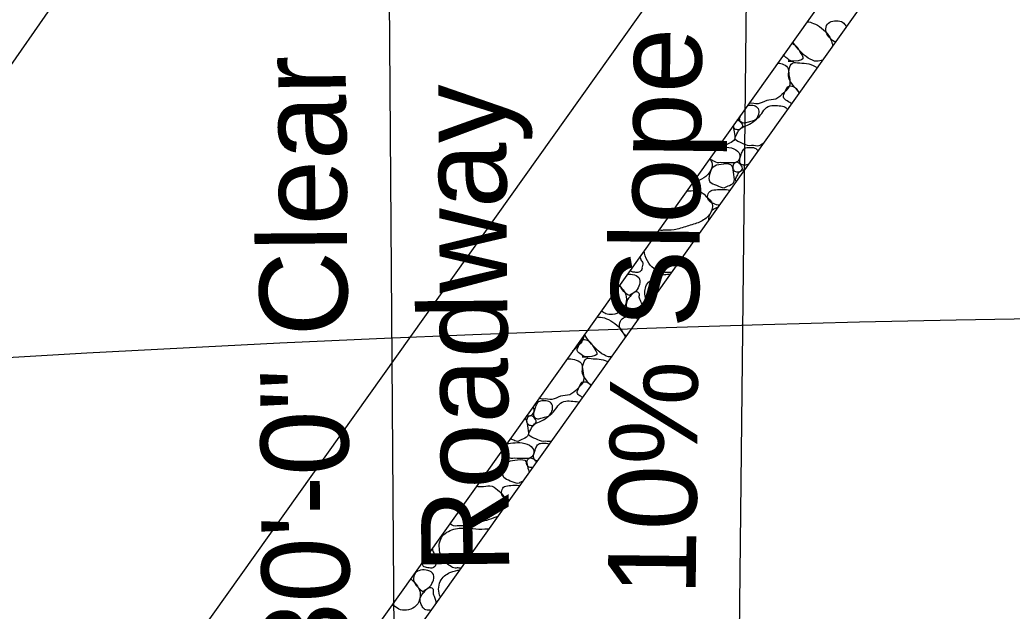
# Model space of a CAD drawing. Extents: x 1385284 to 1385995, y 1975154 to 1975620.
# Drawn here: x 1385473.66 to 1385501.91, y 1975481.13 to 1975497.97 of the extents above; entities that cross this region are included whole.
import ezdxf

# ---------------------------------------------------------------- set-up
doc = ezdxf.new("R2010")
doc.units = 0
for name, color, linetype in [('Default', 7, 'Continuous'), ('R_Horz Alg', 7, 'Continuous'), ('R_Proposed Const Limits', 7, 'Continuous'), ('R_Proposed Road', 7, 'Continuous')]:
    doc.layers.add(name, color=color, linetype=linetype)

msp = doc.modelspace()

# ---------------------------------------------------------------- linework, layer by layer
at = {"layer": 'Default'}
for p, q in [((1385485.913, 1975514.687), (1385460.044, 1975477.467)), ((1385494.416, 1975505.475), (1385494.049, 1975472.644)), ((1385500.579, 1975504.251), (1385472.911, 1975465.371)), ((1385484.136, 1975503.942), (1385484.353, 1975473.943)), ((1385473.726, 1975464.791), (1385501.394, 1975503.671))]:
    msp.add_line(p, q, dxfattribs=at)
for points in [[(1385496.074, 1975497.92), (1385496.093, 1975497.918), (1385496.205, 1975497.901), (1385496.416, 1975497.797), (1385496.673, 1975497.585), (1385496.774, 1975497.365), (1385496.804, 1975497.236), (1385496.806, 1975497.224)], [(1385496.89, 1975497.343), (1385496.839, 1975497.338), (1385496.678, 1975497.49), (1385496.584, 1975497.653), (1385496.634, 1975497.873), (1385496.798, 1975497.946), (1385497.026, 1975497.953), (1385497.155, 1975497.854), (1385497.189, 1975497.78), (1385497.192, 1975497.767)], [(1385495.635, 1975497.304), (1385495.645, 1975497.303), (1385495.706, 1975497.273), (1385495.813, 1975497.177), (1385495.88, 1975497.033), (1385496.067, 1975496.784), (1385495.318, 1975496.801), (1385495.704, 1975496.791), (1385495.695, 1975496.793)], [(1385496.344, 1975496.793), (1385496.273, 1975496.79), (1385496.09, 1975496.874), (1385495.893, 1975497.056), (1385495.749, 1975497.219), (1385495.673, 1975497.327), (1385495.663, 1975497.343)], [(1385495.662, 1975496.793), (1385495.614, 1975496.792), (1385495.518, 1975496.865), (1385495.421, 1975496.931), (1385495.405, 1975496.978), (1385495.405, 1975496.98)], [(1385495.235, 1975496.742), (1385495.269, 1975496.74), (1385495.352, 1975496.724), (1385495.551, 1975496.642), (1385495.543, 1975496.414), (1385495.629, 1975496.103), (1385495.415, 1975495.896), (1385495.193, 1975495.674), (1385494.917, 1975495.706), (1385494.68, 1975495.531), (1385494.514, 1975495.611), (1385494.435, 1975495.59)], [(1385495.861, 1975495.896), (1385495.802, 1975495.958), (1385495.672, 1975496.099), (1385495.525, 1975496.317), (1385495.557, 1975496.543), (1385495.628, 1975496.786), (1385495.857, 1975496.733), (1385496.121, 1975496.738), (1385496.291, 1975496.653), (1385496.367, 1975496.608)], [(1385496.524, 1975496.827), (1385496.464, 1975496.804), (1385496.404, 1975496.793), (1385496.344, 1975496.793)], [(1385495.644, 1975495.592), (1385495.602, 1975495.598), (1385495.512, 1975495.666), (1385495.355, 1975495.755), (1385495.465, 1975495.94), (1385495.512, 1975496.105), (1385495.693, 1975496.079), (1385495.793, 1975495.997), (1385495.832, 1975495.91), (1385495.846, 1975495.876)], [(1385494.435, 1975494.387), (1385494.364, 1975494.383), (1385494.228, 1975494.463), (1385493.969, 1975494.552), (1385494.083, 1975494.721), (1385494.162, 1975494.907), (1385494.386, 1975494.952), (1385494.587, 1975495.11), (1385494.766, 1975495.252), (1385494.861, 1975495.458), (1385495.072, 1975495.551), (1385495.288, 1975495.525), (1385495.468, 1975495.498), (1385495.507, 1975495.43), (1385495.516, 1975495.411)], [(1385494.378, 1975495.537), (1385494.384, 1975495.537), (1385494.462, 1975495.544), (1385494.603, 1975495.542), (1385494.716, 1975495.414), (1385494.692, 1975495.254), (1385494.631, 1975495.137), (1385494.578, 1975495.107)], [(1385494.435, 1975495.59), (1385494.429, 1975495.59), (1385494.422, 1975495.59), (1385494.416, 1975495.59)], [(1385494.168, 1975495.243), (1385494.168, 1975495.236), (1385494.16, 1975495.192), (1385494.128, 1975495.117), (1385494.078, 1975495.11), (1385494.073, 1975495.109)], [(1385494.078, 1975495.115), (1385494.112, 1975495.114), (1385494.186, 1975495.073), (1385494.272, 1975494.93), (1385494.184, 1975494.871), (1385494.15, 1975494.841)], [(1385494.578, 1975495.107), (1385494.531, 1975495.092), (1385494.435, 1975495.069), (1385494.3, 1975495.016), (1385494.173, 1975495.057), (1385494.145, 1975495.148), (1385494.158, 1975495.207), (1385494.167, 1975495.24)], [(1385493.964, 1975494.956), (1385493.98, 1975494.911), (1385493.993, 1975494.793), (1385494.047, 1975494.537), (1385493.863, 1975494.46), (1385493.76, 1975494.412), (1385493.712, 1975494.387)], [(1385494.15, 1975494.841), (1385494.113, 1975494.841), (1385494.028, 1975494.839), (1385493.977, 1975494.902), (1385493.96, 1975494.94), (1385493.958, 1975494.947)], [(1385493.712, 1975494.387), (1385493.669, 1975494.393), (1385493.627, 1975494.406), (1385493.584, 1975494.422)], [(1385494.828, 1975494.445), (1385494.781, 1975494.426), (1385494.665, 1975494.335), (1385494.514, 1975494.408), (1385494.435, 1975494.387)], [(1385493.524, 1975494.337), (1385493.634, 1975494.345), (1385493.857, 1975494.358), (1385494.129, 1975494.248), (1385494.188, 1975494.062), (1385494.092, 1975493.896), (1385493.887, 1975493.904), (1385493.727, 1975493.898), (1385493.607, 1975493.904)], [(1385494.413, 1975493.861), (1385494.372, 1975493.851), (1385494.292, 1975493.815), (1385494.173, 1975493.854), (1385494.146, 1975493.961), (1385494.177, 1975494.075), (1385494.22, 1975494.202), (1385494.281, 1975494.326), (1385494.431, 1975494.342), (1385494.596, 1975494.339), (1385494.665, 1975494.265), (1385494.681, 1975494.238)], [(1385493.299, 1975494.021), (1385493.319, 1975493.995), (1385493.417, 1975493.875), (1385493.313, 1975493.59), (1385493.071, 1975493.42), (1385492.906, 1975493.361), (1385492.808, 1975493.331)], [(1385493.712, 1975493.184), (1385493.64, 1975493.195), (1385493.495, 1975493.264), (1385493.272, 1975493.334), (1385493.275, 1975493.563), (1385493.385, 1975493.808), (1385493.601, 1975493.857), (1385493.962, 1975493.887), (1385493.965, 1975493.646), (1385494.047, 1975493.334), (1385493.863, 1975493.257), (1385493.76, 1975493.209), (1385493.712, 1975493.184)], [(1385493.607, 1975493.904), (1385493.551, 1975493.88), (1385493.425, 1975493.931), (1385493.335, 1975493.986), (1385493.3, 1975494.022)], [(1385494.15, 1975493.638), (1385494.113, 1975493.638), (1385494.028, 1975493.636), (1385493.949, 1975493.718), (1385493.957, 1975493.836), (1385494.041, 1975493.938), (1385494.168, 1975493.888), (1385494.272, 1975493.727), (1385494.184, 1975493.668), (1385494.15, 1975493.638)], [(1385494.058, 1975493.363), (1385494.049, 1975493.374), (1385494.015, 1975493.415), (1385494.083, 1975493.518), (1385494.143, 1975493.666), (1385494.253, 1975493.695), (1385494.308, 1975493.714)], [(1385492.645, 1975493.102), (1385492.664, 1975493.101), (1385492.767, 1975493.091), (1385492.983, 1975493.157), (1385493.187, 1975492.951), (1385493.439, 1975492.747), (1385493.313, 1975492.387), (1385493.025, 1975492.197), (1385492.656, 1975492.096), (1385492.285, 1975491.968), (1385492.052, 1975491.982), (1385491.979, 1975491.985)], [(1385493.582, 1975492.694), (1385493.532, 1975492.686), (1385493.4, 1975492.74), (1385493.245, 1975492.822), (1385493.234, 1975492.988), (1385493.311, 1975493.12), (1385493.531, 1975493.138), (1385493.725, 1975493.149), (1385493.875, 1975493.122), (1385493.885, 1975493.119)], [(1385493.275, 1975492.263), (1385493.273, 1975492.29), (1385493.287, 1975492.392), (1385493.368, 1975492.573), (1385493.492, 1975492.626), (1385493.547, 1975492.644)], [(1385491.756, 1975491.853), (1385491.794, 1975491.871), (1385491.941, 1975491.918), (1385492.258, 1975491.933), (1385492.617, 1975491.86), (1385492.893, 1975491.916), (1385492.988, 1975491.889), (1385493.004, 1975491.882)], [(1385491.979, 1975491.985), (1385491.944, 1975491.967), (1385491.9, 1975491.975), (1385491.857, 1975491.994)], [(1385491.979, 1975490.782), (1385491.911, 1975490.748), (1385491.688, 1975490.886), (1385491.519, 1975491.086), (1385491.438, 1975491.306), (1385491.431, 1975491.396)], [(1385491.308, 1975491.224), (1385491.32, 1975491.196), (1385491.349, 1975491.12), (1385491.424, 1975491.017), (1385491.36, 1975490.914), (1385491.379, 1975490.883)], [(1385490.948, 1975490.717), (1385491.017, 1975490.733), (1385491.166, 1975490.728), (1385491.346, 1975490.61), (1385491.295, 1975490.372), (1385491.182, 1975490.207), (1385491.078, 1975490.16), (1385491.052, 1975490.149)], [(1385491.379, 1975490.883), (1385491.368, 1975490.858), (1385491.32, 1975490.768), (1385491.198, 1975490.783), (1385491.084, 1975490.78), (1385491.037, 1975490.826), (1385491.03, 1975490.833)], [(1385492.22, 1975490.78), (1385492.212, 1975490.779), (1385492.132, 1975490.774), (1385492.052, 1975490.779), (1385491.979, 1975490.782)], [(1385491.563, 1975489.856), (1385491.546, 1975489.882), (1385491.446, 1975490.037), (1385491.444, 1975490.446), (1385491.816, 1975490.699), (1385492.079, 1975490.731), (1385492.182, 1975490.727)], [(1385490.728, 1975490.408), (1385490.74, 1975490.395), (1385490.84, 1975490.282), (1385490.952, 1975490.108), (1385490.914, 1975489.791), (1385490.728, 1975489.619), (1385490.559, 1975489.575), (1385490.475, 1975489.575)], [(1385491.052, 1975490.149), (1385491.021, 1975490.075), (1385490.833, 1975490.242), (1385490.759, 1975490.369), (1385490.741, 1975490.427)], [(1385491.379, 1975489.68), (1385491.368, 1975489.655), (1385491.32, 1975489.565), (1385491.198, 1975489.58), (1385491.019, 1975489.599), (1385490.982, 1975489.715), (1385490.907, 1975489.824), (1385490.946, 1975489.988), (1385491.041, 1975490.1), (1385491.118, 1975490.189), (1385491.197, 1975490.244), (1385491.322, 1975490.193), (1385491.279, 1975490.076), (1385491.341, 1975489.95), (1385491.424, 1975489.814), (1385491.36, 1975489.711), (1385491.379, 1975489.68)], [(1385490.475, 1975489.575), (1385490.404, 1975489.572), (1385490.31, 1975489.614), (1385490.226, 1975489.669), (1385490.21, 1975489.68)], [(1385490.09, 1975489.511), (1385490.147, 1975489.507), (1385490.302, 1975489.498), (1385490.547, 1975489.376), (1385490.774, 1975489.188), (1385490.868, 1975489.008), (1385490.9, 1975488.925)], [(1385490.928, 1975488.964), (1385490.892, 1975488.991), (1385490.794, 1975489.097), (1385490.715, 1975489.232), (1385490.765, 1975489.452), (1385490.929, 1975489.525), (1385491.129, 1975489.533), (1385491.234, 1975489.466), (1385491.264, 1975489.436)], [(1385489.717, 1975488.988), (1385489.717, 1975488.964), (1385489.706, 1975488.834), (1385489.557, 1975488.69), (1385489.447, 1975488.567), (1385489.395, 1975488.534)], [(1385489.792, 1975488.372), (1385489.745, 1975488.372), (1385489.649, 1975488.444), (1385489.486, 1975488.537), (1385489.595, 1975488.723), (1385489.643, 1975488.887), (1385489.824, 1975488.861), (1385489.944, 1975488.757), (1385490.011, 1975488.612), (1385490.198, 1975488.364), (1385489.448, 1975488.381), (1385489.834, 1975488.37), (1385489.826, 1975488.372)], [(1385490.475, 1975488.372), (1385490.404, 1975488.369), (1385490.221, 1975488.453), (1385490.024, 1975488.636), (1385489.85, 1975488.826), (1385489.763, 1975488.968), (1385489.739, 1975489.018)], [(1385489.24, 1975488.317), (1385489.315, 1975488.327), (1385489.439, 1975488.306), (1385489.682, 1975488.221), (1385489.674, 1975487.994), (1385489.76, 1975487.683), (1385489.546, 1975487.475), (1385489.324, 1975487.253), (1385489.047, 1975487.286), (1385488.811, 1975487.11), (1385488.645, 1975487.19), (1385488.566, 1975487.169)], [(1385489.923, 1975487.552), (1385489.89, 1975487.59), (1385489.787, 1975487.709), (1385489.655, 1975487.897), (1385489.688, 1975488.123), (1385489.758, 1975488.365), (1385489.988, 1975488.312), (1385490.214, 1975488.314), (1385490.362, 1975488.258), (1385490.409, 1975488.236)], [(1385490.507, 1975488.373), (1385490.496, 1975488.373), (1385490.486, 1975488.372), (1385490.475, 1975488.372)], [(1385489.683, 1975487.214), (1385489.67, 1975487.223), (1385489.613, 1975487.266), (1385489.486, 1975487.334), (1385489.595, 1975487.52), (1385489.643, 1975487.684), (1385489.824, 1975487.659), (1385489.894, 1975487.609), (1385489.926, 1975487.557)], [(1385488.566, 1975485.966), (1385488.494, 1975485.962), (1385488.359, 1975486.042), (1385488.099, 1975486.131), (1385488.213, 1975486.3), (1385488.292, 1975486.486), (1385488.517, 1975486.531), (1385488.717, 1975486.689), (1385488.897, 1975486.831), (1385488.992, 1975487.037), (1385489.203, 1975487.13), (1385489.407, 1975487.109), (1385489.548, 1975487.097), (1385489.583, 1975487.074)], [(1385488.709, 1975486.686), (1385488.661, 1975486.672), (1385488.565, 1975486.648), (1385488.431, 1975486.595), (1385488.304, 1975486.636), (1385488.277, 1975486.743), (1385488.307, 1975486.857), (1385488.35, 1975486.984), (1385488.411, 1975487.108), (1385488.562, 1975487.125), (1385488.733, 1975487.121), (1385488.846, 1975486.993), (1385488.822, 1975486.833), (1385488.762, 1975486.716), (1385488.709, 1975486.686)], [(1385488.566, 1975487.169), (1385488.525, 1975487.167), (1385488.483, 1975487.178), (1385488.441, 1975487.195)], [(1385488.264, 1975486.946), (1385488.295, 1975486.9), (1385488.313, 1975486.829), (1385488.223, 1975486.678), (1385488.131, 1975486.687), (1385488.085, 1975486.686), (1385488.079, 1975486.686)], [(1385488.039, 1975486.629), (1385488.102, 1975486.562), (1385488.101, 1975486.419), (1385488.178, 1975486.116), (1385487.994, 1975486.039), (1385487.891, 1975485.991), (1385487.842, 1975485.966)], [(1385488.281, 1975486.42), (1385488.244, 1975486.421), (1385488.159, 1975486.418), (1385488.08, 1975486.5), (1385488.088, 1975486.618), (1385488.172, 1975486.72), (1385488.299, 1975486.67), (1385488.403, 1975486.509), (1385488.315, 1975486.45), (1385488.281, 1975486.42)], [(1385487.523, 1975485.904), (1385487.534, 1975485.905), (1385487.687, 1975485.921), (1385487.961, 1975485.95), (1385488.26, 1975485.828), (1385488.319, 1975485.642), (1385488.223, 1975485.475), (1385488.017, 1975485.483), (1385487.857, 1975485.477), (1385487.737, 1975485.484)], [(1385487.842, 1975485.966), (1385487.771, 1975485.977), (1385487.697, 1975486.007), (1385487.623, 1975486.04), (1385487.62, 1975486.041)], [(1385488.79, 1975485.961), (1385488.718, 1975485.951), (1385488.636, 1975485.984), (1385488.566, 1975485.966)], [(1385487.362, 1975485.678), (1385487.411, 1975485.628), (1385487.56, 1975485.497), (1385487.444, 1975485.169), (1385487.155, 1975484.979), (1385486.941, 1975484.908), (1385486.788, 1975484.866), (1385486.783, 1975484.865)], [(1385487.737, 1975485.484), (1385487.682, 1975485.46), (1385487.537, 1975485.517), (1385487.414, 1975485.591), (1385487.377, 1975485.674), (1385487.372, 1975485.692)], [(1385488.398, 1975485.41), (1385488.369, 1975485.409), (1385488.301, 1975485.44), (1385488.277, 1975485.54), (1385488.307, 1975485.654), (1385488.35, 1975485.781), (1385488.411, 1975485.905), (1385488.559, 1975485.921), (1385488.668, 1975485.918), (1385488.737, 1975485.886)], [(1385487.842, 1975484.764), (1385487.771, 1975484.774), (1385487.626, 1975484.843), (1385487.403, 1975484.913), (1385487.406, 1975485.142), (1385487.516, 1975485.387), (1385487.732, 1975485.437), (1385488.093, 1975485.466), (1385488.103, 1975485.259), (1385488.155, 1975485.121), (1385488.165, 1975485.082)], [(1385488.261, 1975485.217), (1385488.231, 1975485.218), (1385488.155, 1975485.221), (1385488.08, 1975485.297), (1385488.088, 1975485.415), (1385488.172, 1975485.517), (1385488.282, 1975485.476), (1385488.359, 1975485.403), (1385488.376, 1975485.379)], [(1385487.989, 1975484.835), (1385487.989, 1975484.835), (1385487.94, 1975484.811), (1385487.891, 1975484.788), (1385487.842, 1975484.764)], [(1385486.658, 1975484.689), (1385486.717, 1975484.685), (1385486.858, 1975484.663), (1385487.114, 1975484.736), (1385487.317, 1975484.53), (1385487.501, 1975484.363), (1385487.511, 1975484.206), (1385487.499, 1975484.146)], [(1385487.603, 1975484.292), (1385487.586, 1975484.299), (1385487.503, 1975484.337), (1385487.376, 1975484.401), (1385487.365, 1975484.567), (1385487.442, 1975484.699), (1385487.634, 1975484.714), (1385487.788, 1975484.723), (1385487.903, 1975484.714)], [(1385487.278, 1975483.835), (1385487.263, 1975483.826), (1385487.103, 1975483.759), (1385486.787, 1975483.675), (1385486.415, 1975483.547), (1385486.182, 1975483.561), (1385486.11, 1975483.564)], [(1385486.11, 1975482.361), (1385486.042, 1975482.327), (1385485.819, 1975482.465), (1385485.604, 1975482.71), (1385485.575, 1975483.228), (1385485.952, 1975483.483), (1385486.388, 1975483.512), (1385486.728, 1975483.45), (1385486.961, 1975483.48), (1385487.024, 1975483.479)], [(1385486.11, 1975483.564), (1385486.051, 1975483.534), (1385485.969, 1975483.576), (1385485.901, 1975483.626)], [(1385485.403, 1975482.926), (1385485.4, 1975482.916), (1385485.417, 1975482.846), (1385485.472, 1975482.733), (1385485.554, 1975482.597), (1385485.491, 1975482.493), (1385485.509, 1975482.463)], [(1385485.183, 1975481.728), (1385485.152, 1975481.654), (1385484.947, 1975481.836), (1385484.845, 1975482.014), (1385484.896, 1975482.235), (1385485.06, 1975482.307), (1385485.287, 1975482.314), (1385485.477, 1975482.19), (1385485.426, 1975481.951), (1385485.313, 1975481.786), (1385485.209, 1975481.739), (1385485.183, 1975481.728)], [(1385485.509, 1975482.463), (1385485.499, 1975482.438), (1385485.451, 1975482.348), (1385485.328, 1975482.362), (1385485.15, 1975482.381), (1385485.132, 1975482.464), (1385485.108, 1975482.506), (1385485.107, 1975482.509)], [(1385485.637, 1975481.529), (1385485.563, 1975481.668), (1385485.579, 1975482.028), (1385485.905, 1975482.26), (1385486.127, 1975482.298), (1385486.187, 1975482.303)], [(1385486.226, 1975482.357), (1385486.187, 1975482.358), (1385486.148, 1975482.36), (1385486.11, 1975482.361)], [(1385484.786, 1975482.058), (1385484.824, 1975482.025), (1385484.958, 1975481.892), (1385485.082, 1975481.687), (1385485.044, 1975481.37), (1385484.859, 1975481.198), (1385484.69, 1975481.154), (1385484.606, 1975481.155)], [(1385485.37, 1975481.154), (1385485.356, 1975481.154), (1385485.294, 1975481.156), (1385485.15, 1975481.178), (1385485.112, 1975481.295), (1385485.038, 1975481.403), (1385485.077, 1975481.567), (1385485.171, 1975481.679), (1385485.248, 1975481.768), (1385485.328, 1975481.824), (1385485.453, 1975481.773), (1385485.41, 1975481.656), (1385485.472, 1975481.53), (1385485.507, 1975481.414), (1385485.511, 1975481.358), (1385485.511, 1975481.352)], [(1385484.606, 1975481.155), (1385484.534, 1975481.151), (1385484.4, 1975481.212), (1385484.301, 1975481.288), (1385484.262, 1975481.322)]]:
    msp.add_open_spline(points, degree=3, dxfattribs=at)
at = {"layer": 'R_Horz Alg'}
msp.add_arc((1385514.357, 1974795.066), 694.494, 77.498258, 106.635112, dxfattribs=at)
at = {"layer": 'R_Proposed Const Limits'}
msp.add_line((1385497.32, 1975506.57), (1385469.652, 1975467.69), dxfattribs=at)
at = {"layer": 'R_Proposed Road'}
msp.add_arc((1385514.357, 1974795.066), 705.494, 77.498258, 106.368381, dxfattribs=at)

# ---------------------------------------------------------------- texts
at = {"layer": 'Default'}
for s, height, rotation, p in [('10% Slope', 2.5, 89.3589, (1385492.899, 1975481.562)), ('30\'-0" Clear', 2.49999, 90.4161, (1385483.063, 1975479.524)), ('Roadway', 2.5, 90.4161, (1385487.595, 1975482.209))]:
    msp.add_text(s, height=height, rotation=rotation, dxfattribs=at).set_placement(p)

doc.saveas('drawing.dxf')
